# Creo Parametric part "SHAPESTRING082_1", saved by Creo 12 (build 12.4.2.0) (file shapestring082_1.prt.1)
Units: Custom; MM, KILOGRAM, SECS

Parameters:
  PTC_WM_ITERATION = "0"
  PTC_WM_VERSION = "-.0"
  PTC_WM_LIFECYCLE_STATE = "In Work"
  PTC_WM_LIFECYCLE = "MO_CADDocument"
  PTC_WM_CREATED_BY = "Maximilian Roepper (Z0017RMS: MO)"
  PTC_WM_CREATED_ON = "18-Sep-26 11:36:42 AM"
  PTC_WM_MODIFIED_BY = "Maximilian Roepper (Z0017RMS: MO)"
  PTC_WM_MODIFIED_ON = "18-Sep-26 11:36:46 AM"
  PDMLINKNUMBER = "PDM000071455241"
  PTC_WM_NAME = "shapestring082_1.prt"
  PTC_WM_NUMBER = "PDM000071455241"

Other parameters: WEIGHT, WEIGHT_FACTOR, WEIGHT_ADD, _MASS_TEMP, _DIFF_TEMP, MC_ERRORS, SUPPLIER

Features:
  1. coordinate system
  2. datum plane "PRT_YZ"
  3. datum plane "PRT_XY"
  4. datum plane "PRT_XZ"
  5. coordinate system
  6. datum axis
  7. datum axis
  8. datum axis
  9. coordinate system
  10. imported feature
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
Other named items: PRT, SIEMENS_MO, DRW_VIEW_ORG, PRT_X, PRT_Y, PRT_Z, CS0, ROUGH_GROB

Layers: 00_STD_CSYS-KSYS, 01_STD_PLANES-EBENEN, 02_STD_AXES-ACHSEN, 03_STD_CSYS-KSYS, 24_IMPORT_FEAT-IMPORT_KE, INTFCLR

Surfaces: 1 plane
